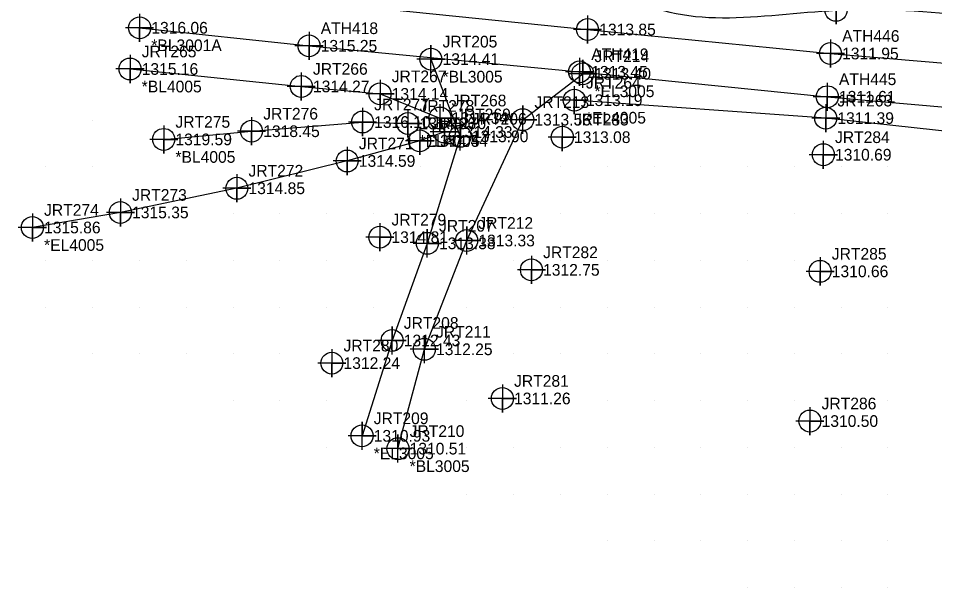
# Model space of a CAD drawing. Extents: x 1234484 to 1235382, y 695050 to 695510.
# Drawn here: x 1234484.1 to 1234680, y 695230 to 695351.8 of the extents above; entities that cross this region are included whole.
import ezdxf

# ---------------------------------------------------------------- set-up
doc = ezdxf.new("R2010")
doc.units = 0
for name, color, linetype in [('Exist DTM Breakline', 7, 'Continuous'), ('Exist DTM Breakline Cogo Comment', 7, 'Continuous'), ('Exist DTM Breakline Cogo Elevation', 7, 'Continuous'), ('Exist DTM Breakline Cogo Number', 7, 'Continuous'), ('Exist DTM Breakline Cogo Point CELL', 7, 'Continuous'), ('Exist DTM Crownline', 7, 'Continuous'), ('Exist DTM Crownline Cogo Elevation', 7, 'Continuous'), ('Exist DTM Crownline Cogo Number', 7, 'Continuous'), ('Exist DTM Crownline Cogo Point CELL', 7, 'Continuous'), ('Exist DTM QL2 LIDAR Elevation Point', 7, 'Continuous'), ('Exist DTM Regular Point CELL', 7, 'Continuous'), ('Exist DTM Regular Point Cogo Elevation', 7, 'Continuous'), ('Exist DTM Regular Point Cogo Number', 7, 'Continuous'), ('Exist Roads EOP', 7, 'Continuous'), ('Exist Roads EOP Cogo Comment', 7, 'Continuous'), ('Exist Roads EOP Cogo Elevation', 7, 'Continuous'), ('Exist Roads EOP Cogo Number', 7, 'Continuous'), ('Exist Roads EOP Cogo Point CELL', 7, 'Continuous'), ('Exist Roads Soil', 7, 'Continuous'), ('Exist Roads Soil Cogo Comment', 7, 'Continuous'), ('Exist Roads Soil Cogo Elevation', 7, 'Continuous'), ('Exist Roads Soil Cogo Number', 7, 'Continuous'), ('Exist Roads Soil Cogo Point CELL', 7, 'Continuous')]:
    doc.layers.add(name, color=color, linetype=linetype)

msp = doc.modelspace()

# ---------------------------------------------------------------- linework, layer by layer
at = {"layer": 'Exist DTM Breakline'}
for points in [[(1234507.969, 695340.963), (1234544.58, 695337.235), (1234561.419, 695335.638), (1234574.228, 695330.465), (1234575.17, 695327.485), (1234569.894, 695325.594), (1234554.391, 695321.283), (1234530.798, 695315.447), (1234505.911, 695310.275), (1234487.091, 695307.055)], [(1234900.418, 695309.093), (1234843.128, 695314.065), (1234821.486, 695313.61), (1234768.142, 695320.476), (1234713.4, 695324.265), (1234656.708, 695330.451), (1234602.942, 695334.287)], [(1234515.178, 695325.901), (1234533.952, 695327.65), (1234557.665, 695329.619), (1234567.366, 695329.311)]]:
    msp.add_lwpolyline(points, dxfattribs=at)
at = {"layer": 'Exist DTM Breakline Cogo Point CELL'}
for points in [[(1234507.969, 695343.963), (1234507.969, 695337.963), (1234507.969, 695340.963), (1234510.969, 695340.963), (1234504.969, 695340.963)], [(1234544.58, 695340.235), (1234544.58, 695334.235), (1234544.58, 695337.235), (1234547.58, 695337.235), (1234541.58, 695337.235)], [(1234561.419, 695338.638), (1234561.419, 695332.638), (1234561.419, 695335.638), (1234564.419, 695335.638), (1234558.419, 695335.638)], [(1234602.942, 695337.287), (1234602.942, 695331.287), (1234602.942, 695334.287), (1234605.942, 695334.287), (1234599.942, 695334.287)], [(1234557.665, 695332.619), (1234557.665, 695326.619), (1234557.665, 695329.619), (1234560.665, 695329.619), (1234554.665, 695329.619)], [(1234567.366, 695332.311), (1234567.366, 695326.311), (1234567.366, 695329.311), (1234570.366, 695329.311), (1234564.366, 695329.311)], [(1234574.228, 695333.465), (1234574.228, 695327.465), (1234574.228, 695330.465), (1234577.228, 695330.465), (1234571.228, 695330.465)], [(1234656.708, 695333.451), (1234656.708, 695327.451), (1234656.708, 695330.451), (1234659.708, 695330.451), (1234653.708, 695330.451)], [(1234533.952, 695330.65), (1234533.952, 695324.65), (1234533.952, 695327.65), (1234536.952, 695327.65), (1234530.952, 695327.65)], [(1234575.17, 695330.485), (1234575.17, 695324.485), (1234575.17, 695327.485), (1234578.17, 695327.485), (1234572.17, 695327.485)], [(1234515.178, 695328.901), (1234515.178, 695322.901), (1234515.178, 695325.901), (1234518.178, 695325.901), (1234512.178, 695325.901)], [(1234569.894, 695328.594), (1234569.894, 695322.594), (1234569.894, 695325.594), (1234572.894, 695325.594), (1234566.894, 695325.594)], [(1234554.391, 695324.283), (1234554.391, 695318.283), (1234554.391, 695321.283), (1234557.391, 695321.283), (1234551.391, 695321.283)], [(1234530.798, 695318.447), (1234530.798, 695312.447), (1234530.798, 695315.447), (1234533.798, 695315.447), (1234527.798, 695315.447)], [(1234505.911, 695313.275), (1234505.911, 695307.275), (1234505.911, 695310.275), (1234508.911, 695310.275), (1234502.911, 695310.275)], [(1234487.091, 695310.055), (1234487.091, 695304.055), (1234487.091, 695307.055), (1234490.091, 695307.055), (1234484.091, 695307.055)]]:
    msp.add_lwpolyline(points, dxfattribs=at)
for centre in [(1234507.969, 695340.963), (1234544.58, 695337.235), (1234561.419, 695335.638), (1234602.942, 695334.287), (1234557.665, 695329.619), (1234574.228, 695330.465), (1234656.708, 695330.451), (1234533.952, 695327.65), (1234567.366, 695329.311), (1234575.17, 695327.485), (1234515.178, 695325.901), (1234569.894, 695325.594), (1234554.391, 695321.283), (1234530.798, 695315.447), (1234505.911, 695310.275), (1234487.091, 695307.055)]:
    msp.add_circle(centre, 2.344, dxfattribs=at)
at = {"layer": 'Exist DTM Crownline'}
msp.add_lwpolyline([(1234511.603, 695359.057), (1234605.73, 695349.422), (1234657.657, 695344.297), (1234715.146, 695339.445), (1234769.335, 695334.825), (1234822.546, 695330.321), (1234845.176, 695328.304), (1234903.738, 695322.57)], dxfattribs=at)
at = {"layer": 'Exist DTM Crownline Cogo Point CELL'}
for points in [[(1234605.787, 695352.401), (1234605.787, 695346.401), (1234605.787, 695349.401), (1234608.787, 695349.401), (1234602.787, 695349.401)], [(1234657.714, 695347.276), (1234657.714, 695341.276), (1234657.714, 695344.276), (1234660.714, 695344.276), (1234654.714, 695344.276)]]:
    msp.add_lwpolyline(points, dxfattribs=at)
for centre in [(1234605.787, 695349.401), (1234657.714, 695344.276)]:
    msp.add_circle(centre, 2.344, dxfattribs=at)
at = {"layer": 'Exist DTM QL2 LIDAR Elevation Point'}
for p, q in [((1234500, 695330), (1234500, 695330)), ((1234490, 695320), (1234490, 695320)), ((1234500, 695320), (1234500, 695320)), ((1234570, 695320), (1234570, 695320)), ((1234600, 695320), (1234600, 695320)), ((1234610, 695320), (1234610, 695320)), ((1234620, 695320), (1234620, 695320)), ((1234630, 695320), (1234630, 695320)), ((1234640, 695320), (1234640, 695320)), ((1234650, 695320), (1234650, 695320)), ((1234660, 695320), (1234660, 695320)), ((1234670, 695320), (1234670, 695320)), ((1234530, 695310), (1234530, 695310)), ((1234540, 695310), (1234540, 695310)), ((1234550, 695310), (1234550, 695310)), ((1234560, 695310), (1234560, 695310)), ((1234590, 695310), (1234590, 695310)), ((1234600, 695310), (1234600, 695310)), ((1234610, 695310), (1234610, 695310)), ((1234620, 695310), (1234620, 695310)), ((1234630, 695310), (1234630, 695310)), ((1234640, 695310), (1234640, 695310)), ((1234650, 695310), (1234650, 695310)), ((1234660, 695310), (1234660, 695310)), ((1234670, 695310), (1234670, 695310)), ((1234490, 695300), (1234490, 695300)), ((1234500, 695300), (1234500, 695300)), ((1234510, 695300), (1234510, 695300)), ((1234520, 695300), (1234520, 695300)), ((1234530, 695300), (1234530, 695300)), ((1234540, 695300), (1234540, 695300)), ((1234550, 695300), (1234550, 695300)), ((1234560, 695300), (1234560, 695300)), ((1234590, 695300), (1234590, 695300)), ((1234600, 695300), (1234600, 695300)), ((1234610, 695300), (1234610, 695300)), ((1234620, 695300), (1234620, 695300)), ((1234630, 695300), (1234630, 695300)), ((1234640, 695300), (1234640, 695300)), ((1234650, 695300), (1234650, 695300)), ((1234660, 695300), (1234660, 695300)), ((1234670, 695300), (1234670, 695300)), ((1234490, 695290), (1234490, 695290)), ((1234500, 695290), (1234500, 695290)), ((1234510, 695290), (1234510, 695290)), ((1234520, 695290), (1234520, 695290)), ((1234530, 695290), (1234530, 695290)), ((1234540, 695290), (1234540, 695290)), ((1234550, 695290), (1234550, 695290)), ((1234560, 695290), (1234560, 695290)), ((1234580, 695290), (1234580, 695290)), ((1234590, 695290), (1234590, 695290)), ((1234600, 695290), (1234600, 695290)), ((1234610, 695290), (1234610, 695290)), ((1234620, 695290), (1234620, 695290)), ((1234630, 695290), (1234630, 695290)), ((1234640, 695290), (1234640, 695290)), ((1234650, 695290), (1234650, 695290)), ((1234660, 695290), (1234660, 695290)), ((1234670, 695290), (1234670, 695290)), ((1234500, 695280), (1234500, 695280)), ((1234510, 695280), (1234510, 695280)), ((1234520, 695280), (1234520, 695280)), ((1234530, 695280), (1234530, 695280)), ((1234540, 695280), (1234540, 695280)), ((1234550, 695280), (1234550, 695280)), ((1234580, 695280), (1234580, 695280)), ((1234590, 695280), (1234590, 695280)), ((1234600, 695280), (1234600, 695280)), ((1234610, 695280), (1234610, 695280)), ((1234620, 695280), (1234620, 695280)), ((1234630, 695280), (1234630, 695280)), ((1234640, 695280), (1234640, 695280)), ((1234650, 695280), (1234650, 695280)), ((1234660, 695280), (1234660, 695280)), ((1234670, 695280), (1234670, 695280)), ((1234530, 695270), (1234530, 695270)), ((1234540, 695270), (1234540, 695270)), ((1234550, 695270), (1234550, 695270)), ((1234580, 695270), (1234580, 695270)), ((1234590, 695270), (1234590, 695270)), ((1234600, 695270), (1234600, 695270)), ((1234610, 695270), (1234610, 695270)), ((1234620, 695270), (1234620, 695270)), ((1234630, 695270), (1234630, 695270)), ((1234640, 695270), (1234640, 695270)), ((1234650, 695270), (1234650, 695270)), ((1234660, 695270), (1234660, 695270)), ((1234670, 695270), (1234670, 695270)), ((1234550, 695260), (1234550, 695260)), ((1234570, 695260), (1234570, 695260)), ((1234580, 695260), (1234580, 695260)), ((1234590, 695260), (1234590, 695260)), ((1234600, 695260), (1234600, 695260)), ((1234610, 695260), (1234610, 695260)), ((1234620, 695260), (1234620, 695260)), ((1234630, 695260), (1234630, 695260)), ((1234640, 695260), (1234640, 695260)), ((1234650, 695260), (1234650, 695260)), ((1234660, 695260), (1234660, 695260)), ((1234670, 695260), (1234670, 695260)), ((1234580, 695250), (1234580, 695250)), ((1234590, 695250), (1234590, 695250)), ((1234600, 695250), (1234600, 695250)), ((1234610, 695250), (1234610, 695250)), ((1234620, 695250), (1234620, 695250)), ((1234630, 695250), (1234630, 695250)), ((1234640, 695250), (1234640, 695250)), ((1234650, 695250), (1234650, 695250)), ((1234660, 695250), (1234660, 695250)), ((1234670, 695250), (1234670, 695250)), ((1234610, 695240), (1234610, 695240)), ((1234620, 695240), (1234620, 695240)), ((1234630, 695240), (1234630, 695240)), ((1234640, 695240), (1234640, 695240)), ((1234650, 695240), (1234650, 695240)), ((1234660, 695240), (1234660, 695240)), ((1234670, 695240), (1234670, 695240)), ((1234640, 695230), (1234640, 695230)), ((1234650, 695230), (1234650, 695230)), ((1234660, 695230), (1234660, 695230)), ((1234670, 695230), (1234670, 695230))]:
    msp.add_line(p, q, dxfattribs=at)
at = {"layer": 'Exist DTM Regular Point CELL'}
for points in [[(1234600.383, 695329.379), (1234600.383, 695323.379), (1234600.383, 695326.379), (1234603.383, 695326.379), (1234597.383, 695326.379)], [(1234656.188, 695325.624), (1234656.188, 695319.624), (1234656.188, 695322.624), (1234659.188, 695322.624), (1234653.188, 695322.624)], [(1234561.37, 695307.981), (1234561.37, 695301.981), (1234561.37, 695304.981), (1234564.37, 695304.981), (1234558.37, 695304.981)], [(1234593.784, 695300.996), (1234593.784, 695294.996), (1234593.784, 695297.996), (1234596.784, 695297.996), (1234590.784, 695297.996)], [(1234655.503, 695300.674), (1234655.503, 695294.674), (1234655.503, 695297.674), (1234658.503, 695297.674), (1234652.503, 695297.674)], [(1234551.113, 695281.042), (1234551.113, 695275.042), (1234551.113, 695278.042), (1234554.113, 695278.042), (1234548.113, 695278.042)], [(1234587.574, 695273.479), (1234587.574, 695267.479), (1234587.574, 695270.479), (1234590.574, 695270.479), (1234584.574, 695270.479)], [(1234653.324, 695268.645), (1234653.324, 695262.645), (1234653.324, 695265.645), (1234656.324, 695265.645), (1234650.324, 695265.645)]]:
    msp.add_lwpolyline(points, dxfattribs=at)
for centre in [(1234600.383, 695326.379), (1234656.188, 695322.624), (1234561.37, 695304.981), (1234593.784, 695297.996), (1234655.503, 695297.674), (1234551.113, 695278.042), (1234587.574, 695270.479), (1234653.324, 695265.645)]:
    msp.add_circle(centre, 2.344, dxfattribs=at)
at = {"layer": 'Exist Roads EOP'}
msp.add_lwpolyline([(1234510.022, 695349.783), (1234546.237, 695345.927), (1234604.07, 695340.356), (1234657.035, 695335.026), (1234714.094, 695329.996), (1234768.395, 695325.598), (1234821.671, 695320.933), (1234844.56, 695319.029)], dxfattribs=at)
msp.add_spline([(1234605.599, 695398.165), (1234601.696, 695381.855), (1234613.593, 695357.692), (1234658.916, 695353.52), (1234716.264, 695348.291), (1234770.499, 695343.743), (1234823.09, 695339.258), (1234845.762, 695337.371), (1234903.754, 695331.785), (1234928.613, 695329.389)], degree=3, dxfattribs=at)
at = {"layer": 'Exist Roads EOP Cogo Point CELL'}
for points in [[(1234658.916, 695356.52), (1234658.916, 695350.52), (1234658.916, 695353.52), (1234661.916, 695353.52), (1234655.916, 695353.52)], [(1234510.022, 695352.783), (1234510.022, 695346.783), (1234510.022, 695349.783), (1234513.022, 695349.783), (1234507.022, 695349.783)], [(1234546.237, 695348.927), (1234546.237, 695342.927), (1234546.237, 695345.927), (1234549.237, 695345.927), (1234543.237, 695345.927)], [(1234604.07, 695343.356), (1234604.07, 695337.356), (1234604.07, 695340.356), (1234607.07, 695340.356), (1234601.07, 695340.356)], [(1234657.035, 695338.026), (1234657.035, 695332.026), (1234657.035, 695335.026), (1234660.035, 695335.026), (1234654.035, 695335.026)]]:
    msp.add_lwpolyline(points, dxfattribs=at)
for centre in [(1234658.916, 695353.52), (1234510.022, 695349.783), (1234546.237, 695345.927), (1234604.07, 695340.356), (1234657.035, 695335.026)]:
    msp.add_circle(centre, 2.344, dxfattribs=at)
at = {"layer": 'Exist Roads Soil'}
for points in [[(1234572.294, 695343.07), (1234578.556, 695326.555), (1234571.532, 695303.664), (1234563.999, 695282.88), (1234557.574, 695262.487)], [(1234565.247, 695259.747), (1234570.895, 695280.996), (1234579.943, 695304.27), (1234591.925, 695330.122), (1234604.76, 695339.94)]]:
    msp.add_lwpolyline(points, dxfattribs=at)
at = {"layer": 'Exist Roads Soil Cogo Point CELL'}
for points in [[(1234572.294, 695340.07), (1234572.294, 695346.07), (1234572.294, 695343.07), (1234575.294, 695343.07), (1234569.294, 695343.07)], [(1234604.76, 695336.94), (1234604.76, 695342.94), (1234604.76, 695339.94), (1234607.76, 695339.94), (1234601.76, 695339.94)], [(1234591.925, 695327.122), (1234591.925, 695333.122), (1234591.925, 695330.122), (1234594.925, 695330.122), (1234588.925, 695330.122)], [(1234578.556, 695323.555), (1234578.556, 695329.555), (1234578.556, 695326.555), (1234581.556, 695326.555), (1234575.556, 695326.555)], [(1234571.532, 695300.664), (1234571.532, 695306.664), (1234571.532, 695303.664), (1234574.532, 695303.664), (1234568.532, 695303.664)], [(1234579.943, 695301.27), (1234579.943, 695307.27), (1234579.943, 695304.27), (1234582.943, 695304.27), (1234576.943, 695304.27)], [(1234563.999, 695279.88), (1234563.999, 695285.88), (1234563.999, 695282.88), (1234566.999, 695282.88), (1234560.999, 695282.88)], [(1234570.895, 695277.996), (1234570.895, 695283.996), (1234570.895, 695280.996), (1234573.895, 695280.996), (1234567.895, 695280.996)], [(1234557.574, 695259.487), (1234557.574, 695265.487), (1234557.574, 695262.487), (1234560.574, 695262.487), (1234554.574, 695262.487)], [(1234565.247, 695256.747), (1234565.247, 695262.747), (1234565.247, 695259.747), (1234568.247, 695259.747), (1234562.247, 695259.747)]]:
    msp.add_lwpolyline(points, dxfattribs=at)
for centre in [(1234572.294, 695343.07), (1234604.76, 695339.94), (1234591.925, 695330.122), (1234578.556, 695326.555), (1234579.943, 695304.27), (1234571.532, 695303.664), (1234563.999, 695282.88), (1234570.895, 695280.996), (1234557.574, 695262.487), (1234565.247, 695259.747)]:
    msp.add_circle(centre, 2.344, dxfattribs=at)

# ---------------------------------------------------------------- texts
at = {"layer": 'Exist DTM Breakline Cogo Comment'}
for s, p in [('*BL4005', (1234510.469, 695335.963)), ('*EL4005', (1234605.442, 695329.287)), ('*EL4005', (1234569.866, 695324.311)), ('*BL4005', (1234517.678, 695320.901)), ('*EL4005', (1234489.591, 695302.055))]:
    msp.add_text(s, height=2.5, dxfattribs=at).set_placement(p)
at = {"layer": 'Exist DTM Breakline Cogo Elevation'}
for s, p in [('1315.16', (1234510.469, 695339.713)), ('1314.27', (1234547.08, 695335.985)), ('1314.14', (1234563.919, 695334.388)), ('1313.19', (1234605.442, 695333.037)), ('1316.10', (1234560.165, 695328.369)), ('1314.96', (1234569.866, 695328.061)), ('1314.34', (1234576.728, 695329.215)), ('1311.39', (1234659.208, 695329.201)), ('1318.45', (1234536.452, 695326.4)), ('1314.33', (1234577.67, 695326.235)), ('1319.59', (1234517.678, 695324.651)), ('1314.44', (1234572.394, 695324.344)), ('1314.59', (1234556.891, 695320.033)), ('1314.85', (1234533.298, 695314.197)), ('1315.35', (1234508.411, 695309.025)), ('1315.86', (1234489.591, 695305.805))]:
    msp.add_text(s, height=2.5, dxfattribs=at).set_placement(p)
at = {"layer": 'Exist DTM Breakline Cogo Number'}
for s, p in [('JRT265', (1234510.469, 695343.463)), ('JRT266', (1234547.08, 695339.735)), ('JRT267', (1234563.919, 695338.138)), ('JRT264', (1234605.442, 695336.787)), ('JRT277', (1234560.165, 695332.119)), ('JRT278', (1234569.866, 695331.811)), ('JRT268', (1234576.728, 695332.965)), ('JRT263', (1234659.208, 695332.951)), ('JRT276', (1234536.452, 695330.15)), ('JRT269', (1234577.67, 695329.985)), ('JRT275', (1234517.678, 695328.401)), ('JRT270', (1234572.394, 695328.094)), ('JRT271', (1234556.891, 695323.783)), ('JRT272', (1234533.298, 695317.947)), ('JRT273', (1234508.411, 695312.775)), ('JRT274', (1234489.591, 695309.555))]:
    msp.add_text(s, height=2.5, dxfattribs=at).set_placement(p)
at = {"layer": 'Exist DTM Crownline Cogo Elevation'}
for s, p in [('1313.85', (1234608.287, 695348.151)), ('1311.95', (1234660.214, 695343.026))]:
    msp.add_text(s, height=2.5, dxfattribs=at).set_placement(p)
at = {"layer": 'Exist DTM Crownline Cogo Number'}
msp.add_text('ATH446', height=2.5, dxfattribs=at).set_placement((1234660.214, 695346.776))
at = {"layer": 'Exist DTM Regular Point Cogo Elevation'}
for s, p in [('1313.08', (1234602.883, 695325.129)), ('1310.69', (1234658.688, 695321.374)), ('1314.81', (1234563.87, 695303.731)), ('1312.75', (1234596.284, 695296.746)), ('1310.66', (1234658.003, 695296.424)), ('1312.24', (1234553.613, 695276.792)), ('1311.26', (1234590.074, 695269.229)), ('1310.50', (1234655.824, 695264.395))]:
    msp.add_text(s, height=2.5, dxfattribs=at).set_placement(p)
at = {"layer": 'Exist DTM Regular Point Cogo Number'}
for s, p in [('JRT283', (1234602.883, 695328.879)), ('JRT284', (1234658.688, 695325.124)), ('JRT279', (1234563.87, 695307.481)), ('JRT282', (1234596.284, 695300.496)), ('JRT285', (1234658.003, 695300.174)), ('JRT280', (1234553.613, 695280.542)), ('JRT281', (1234590.074, 695272.979)), ('JRT286', (1234655.824, 695268.145))]:
    msp.add_text(s, height=2.5, dxfattribs=at).set_placement(p)
at = {"layer": 'Exist Roads EOP Cogo Comment'}
msp.add_text('*BL3001A', height=2.5, dxfattribs=at).set_placement((1234512.522, 695344.783))
at = {"layer": 'Exist Roads EOP Cogo Elevation'}
for s, p in [('1316.06', (1234512.522, 695348.533)), ('1315.25', (1234548.737, 695344.677)), ('1313.45', (1234606.57, 695339.106)), ('1311.61', (1234659.535, 695333.776))]:
    msp.add_text(s, height=2.5, dxfattribs=at).set_placement(p)
at = {"layer": 'Exist Roads EOP Cogo Number'}
for s, p in [('ATH418', (1234548.737, 695348.427)), ('ATH419', (1234606.57, 695342.856)), ('ATH445', (1234659.535, 695337.526))]:
    msp.add_text(s, height=2.5, dxfattribs=at).set_placement(p)
at = {"layer": 'Exist Roads Soil Cogo Comment'}
for s, p in [('*BL3005', (1234574.794, 695338.07)), ('*EL3005', (1234607.26, 695334.94)), ('*EL3005', (1234560.074, 695257.487)), ('*BL3005', (1234567.747, 695254.747))]:
    msp.add_text(s, height=2.5, dxfattribs=at).set_placement(p)
at = {"layer": 'Exist Roads Soil Cogo Elevation'}
for s, p in [('1314.41', (1234574.794, 695341.82)), ('1313.40', (1234607.26, 695338.69)), ('1313.56', (1234594.425, 695328.872)), ('1313.90', (1234581.056, 695325.305)), ('1313.38', (1234574.032, 695302.414)), ('1313.33', (1234582.443, 695303.02)), ('1312.43', (1234566.499, 695281.63)), ('1312.25', (1234573.395, 695279.746)), ('1310.93', (1234560.074, 695261.237)), ('1310.51', (1234567.747, 695258.497))]:
    msp.add_text(s, height=2.5, dxfattribs=at).set_placement(p)
at = {"layer": 'Exist Roads Soil Cogo Number'}
for s, p in [('JRT205', (1234574.794, 695345.57)), ('JRT214', (1234607.26, 695342.44)), ('JRT213', (1234594.425, 695332.622)), ('JRT206', (1234581.056, 695329.055)), ('JRT207', (1234574.032, 695306.164)), ('JRT212', (1234582.443, 695306.77)), ('JRT208', (1234566.499, 695285.38)), ('JRT211', (1234573.395, 695283.496)), ('JRT209', (1234560.074, 695264.987)), ('JRT210', (1234567.747, 695262.247))]:
    msp.add_text(s, height=2.5, dxfattribs=at).set_placement(p)

doc.saveas('drawing.dxf')
